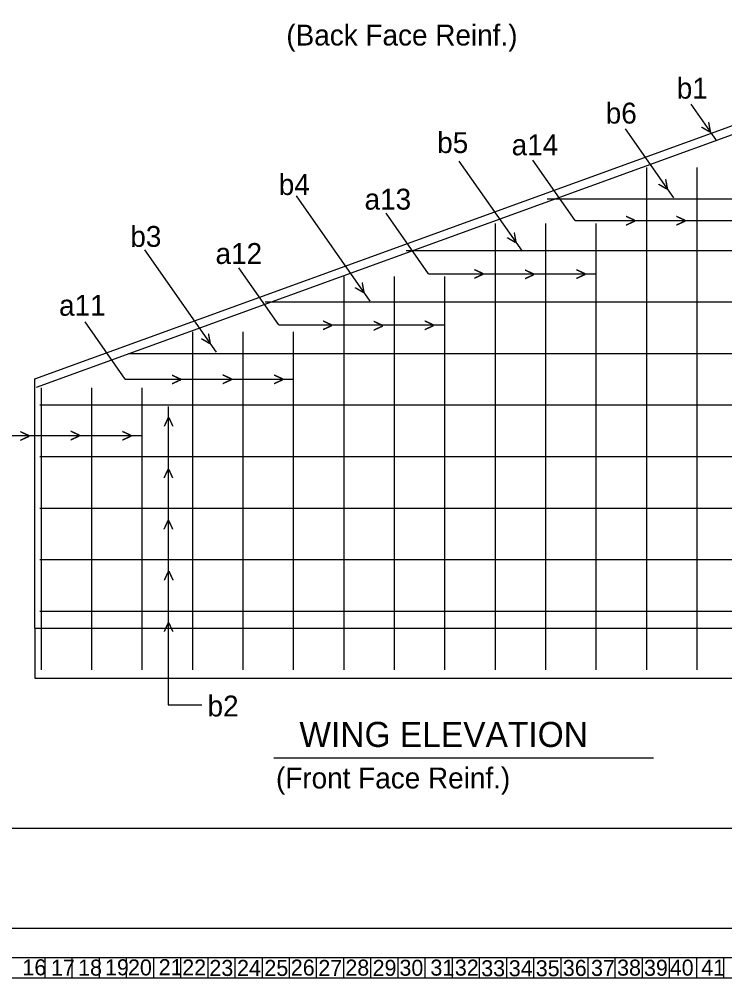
# Model space of a CAD drawing. Extents: x -0.08 to 2.83, y -0.03 to 1.92.
# Drawn here: x 0.36 to 0.8, y -0.031 to 0.567 of the extents above; entities that cross this region are included whole.
import ezdxf

# ---------------------------------------------------------------- set-up
doc = ezdxf.new("R2010")
doc.units = 0
for name, color, linetype in [('16', 7, 'Continuous'), ('17', 7, 'Continuous'), ('18', 7, 'Continuous'), ('19', 7, 'Continuous'), ('20', 7, 'Continuous'), ('21', 7, 'Continuous'), ('22', 7, 'Continuous'), ('23', 7, 'Continuous'), ('24', 7, 'Continuous'), ('25', 7, 'Continuous'), ('26', 7, 'Continuous'), ('27', 7, 'Continuous'), ('28', 7, 'Continuous'), ('29', 7, 'Continuous'), ('30', 7, 'Continuous'), ('31', 7, 'Continuous'), ('32', 7, 'Continuous'), ('33', 7, 'Continuous'), ('34', 7, 'Continuous'), ('35', 7, 'Continuous'), ('36', 7, 'Continuous'), ('37', 7, 'Continuous'), ('38', 7, 'Continuous'), ('39', 7, 'Continuous'), ('40', 7, 'Continuous'), ('41', 7, 'Continuous'), ('50', 7, 'Continuous'), ('51', 7, 'Continuous'), ('55', 7, 'Continuous'), ('57', 7, 'Continuous'), ('62', 7, 'Continuous'), ('63', 7, 'Continuous')]:
    doc.layers.add(name, color=color, linetype=linetype)

msp = doc.modelspace()

# ---------------------------------------------------------------- linework, layer by layer
at = {"layer": '50'}
for p, q in [((0.36956, 0.34269), (0.80997, 0.50242)), ((0.37071, 0.33757), (0.81174, 0.49752)), ((0.36956, 0.18732), (0.36956, 0.34269)), ((0.36956, 0.18732), (0.36956, 0.15607)), ((0.36956, 0.18732), (0.91992, 0.18732)), ((0.36956, 0.15607), (0.88809, 0.15607))]:
    msp.add_line(p, q, dxfattribs=at)
at = {"layer": '51'}
for p, q in [((0.75129, 0.16127), (0.75129, 0.47444)), ((0.78275, 0.16127), (0.78275, 0.47444)), ((0.81865, 0.45467), (0.68924, 0.45467)), ((0.65689, 0.16127), (0.65689, 0.43955)), ((0.68835, 0.16127), (0.68835, 0.43955)), ((0.71982, 0.16127), (0.71982, 0.43955)), ((0.81865, 0.42255), (0.6013, 0.42255)), ((0.56249, 0.16127), (0.56249, 0.40646)), ((0.59395, 0.16127), (0.59395, 0.40646)), ((0.62542, 0.16127), (0.62542, 0.40646)), ((0.81865, 0.39044), (0.51335, 0.39044)), ((0.46809, 0.16127), (0.46809, 0.37202)), ((0.49955, 0.16127), (0.49955, 0.37202)), ((0.53102, 0.16127), (0.53102, 0.37202)), ((0.81865, 0.35832), (0.42799, 0.35832)), ((0.37369, 0.16127), (0.37369, 0.33714)), ((0.40515, 0.16127), (0.40515, 0.33714)), ((0.43662, 0.16127), (0.43662, 0.33714)), ((0.81865, 0.3262), (0.37282, 0.3262)), ((0.81865, 0.29408), (0.37282, 0.29408)), ((0.81865, 0.26196), (0.37282, 0.26196)), ((0.81865, 0.22984), (0.37282, 0.22984)), ((0.81865, 0.19773), (0.37282, 0.19773)), ((0.37369, 0.16127), (0.37369, 0.16127)), ((0.40515, 0.16127), (0.40515, 0.16127)), ((0.43663, 0.16127), (0.43663, 0.16127)), ((0.4681, 0.16127), (0.4681, 0.16127)), ((0.46968, 0.16127), (0.46968, 0.16127)), ((0.50115, 0.16127), (0.50115, 0.16127)), ((0.56253, 0.16127), (0.56253, 0.16127)), ((0.59399, 0.16127), (0.59399, 0.16127)), ((0.62547, 0.16127), (0.62547, 0.16127)), ((0.65694, 0.16127), (0.65694, 0.16127)), ((0.68842, 0.16127), (0.68842, 0.16127)), ((0.71989, 0.16127), (0.71989, 0.16127)), ((0.75136, 0.16127), (0.75136, 0.16127)), ((0.78284, 0.16127), (0.78284, 0.16127))]:
    msp.add_line(p, q, dxfattribs=at)
at = {"layer": '55'}
for p, q in [((0.79494, 0.49115), (0.77896, 0.514)), ((0.76814, 0.45556), (0.73803, 0.49858)), ((0.67373, 0.42224), (0.63436, 0.4785)), ((0.70674, 0.44133), (0.68028, 0.47914)), ((0.57888, 0.39108), (0.53294, 0.4567)), ((0.6152, 0.40819), (0.58868, 0.44609)), ((0.70674, 0.44133), (0.81422, 0.44133)), ((0.48299, 0.35926), (0.43827, 0.42317)), ((0.5218, 0.37627), (0.49689, 0.41186)), ((0.6152, 0.40819), (0.71983, 0.40819)), ((0.42604, 0.34258), (0.40106, 0.37828)), ((0.5218, 0.37627), (0.62524, 0.37627)), ((0.42604, 0.34258), (0.53126, 0.34258)), ((0.45288, 0.32544), (0.45288, 0.13949)), ((0.34063, 0.3074), (0.43662, 0.3074))]:
    msp.add_line(p, q, dxfattribs=at)
at = {"layer": '57'}
for p, q in [((0.45288, 0.13949), (0.47372, 0.13949)), ((0.51877, 0.10649), (0.75544, 0.10649))]:
    msp.add_line(p, q, dxfattribs=at)
at = {"layer": '62'}
for p, q in [((0.10494, -0.01804), (1.17174, -0.01804)), ((0.37588, -0.01804), (0.37588, -0.03074)), ((0.39281, -0.01804), (0.39281, -0.03074)), ((0.40974, -0.01804), (0.40974, -0.03074)), ((0.42668, -0.01804), (0.42668, -0.03074)), ((0.44361, -0.01804), (0.44361, -0.03074)), ((0.46054, -0.01804), (0.46054, -0.03074)), ((0.47748, -0.01804), (0.47748, -0.03074)), ((0.49441, -0.01804), (0.49441, -0.03074)), ((0.51134, -0.01804), (0.51134, -0.03074)), ((0.52828, -0.01804), (0.52828, -0.03074)), ((0.54521, -0.01804), (0.54521, -0.03074)), ((0.56214, -0.01804), (0.56214, -0.03074)), ((0.57908, -0.01804), (0.57908, -0.03074)), ((0.59601, -0.01804), (0.59601, -0.03074)), ((0.61294, -0.01804), (0.61294, -0.03074)), ((0.62988, -0.01804), (0.62988, -0.03074)), ((0.64681, -0.01804), (0.64681, -0.03074)), ((0.66374, -0.01804), (0.66374, -0.03074)), ((0.68068, -0.01804), (0.68068, -0.03074)), ((0.69761, -0.01804), (0.69761, -0.03074)), ((0.71454, -0.01804), (0.71454, -0.03074)), ((0.73147, -0.01804), (0.73147, -0.03074)), ((0.74841, -0.01804), (0.74841, -0.03074)), ((0.76534, -0.01804), (0.76534, -0.03074)), ((0.78228, -0.01804), (0.78228, -0.03074)), ((0.79921, -0.01804), (0.79921, -0.03074)), ((0.10494, -0.03074), (1.17174, -0.03074))]:
    msp.add_line(p, q, dxfattribs=at)
at = {"layer": '63'}
msp.add_line((2.83333, 0), (0, 0), dxfattribs=at)
msp.add_lwpolyline([(0.16668, 0.06244), (0.16668, 1.77077), (2.72918, 1.77077), (2.72918, 0.10411), (2.56251, 0.10411), (2.56251, 0.14578), (2.07387, 0.14578), (2.07387, 0.06244)], close=True, dxfattribs=at)

# ---------------------------------------------------------------- texts
at = {"layer": '16'}
msp.add_text('16', height=0.01, rotation=360, dxfattribs=at).set_placement((0.3619, -0.02918))
at = {"layer": '17'}
msp.add_text('17', height=0.01, rotation=360, dxfattribs=at).set_placement((0.3797, -0.02946))
at = {"layer": '18'}
msp.add_text('18', height=0.01, rotation=360, dxfattribs=at).set_placement((0.39663, -0.02938))
at = {"layer": '19'}
msp.add_text('19', height=0.01, rotation=360, dxfattribs=at).set_placement((0.4134, -0.02918))
at = {"layer": '20'}
msp.add_text('20', height=0.01, rotation=360, dxfattribs=at).set_placement((0.42774, -0.02926))
at = {"layer": '21'}
msp.add_text('21', height=0.01, rotation=360, dxfattribs=at).set_placement((0.44688, -0.02909))
at = {"layer": '22'}
msp.add_text('22', height=0.01, rotation=360, dxfattribs=at).set_placement((0.46158, -0.02929))
at = {"layer": '23'}
msp.add_text('23', height=0.01, rotation=360, dxfattribs=at).set_placement((0.47852, -0.02958))
at = {"layer": '24'}
msp.add_text('24', height=0.01, rotation=360, dxfattribs=at).set_placement((0.49576, -0.02958))
at = {"layer": '25'}
msp.add_text('25', height=0.01, rotation=360, dxfattribs=at).set_placement((0.51281, -0.02958))
at = {"layer": '26'}
msp.add_text('26', height=0.01, rotation=360, dxfattribs=at).set_placement((0.52931, -0.02936))
at = {"layer": '27'}
msp.add_text('27', height=0.01, rotation=360, dxfattribs=at).set_placement((0.54648, -0.02958))
at = {"layer": '28'}
msp.add_text('28', height=0.01, rotation=360, dxfattribs=at).set_placement((0.56333, -0.02938))
at = {"layer": '29'}
msp.add_text('29', height=0.01, rotation=360, dxfattribs=at).set_placement((0.58032, -0.02956))
at = {"layer": '30'}
msp.add_text('30', height=0.01, rotation=360, dxfattribs=at).set_placement((0.59706, -0.02946))
at = {"layer": '31'}
msp.add_text('31', height=0.01, rotation=360, dxfattribs=at).set_placement((0.61636, -0.02938))
at = {"layer": '32'}
msp.add_text('32', height=0.01, rotation=360, dxfattribs=at).set_placement((0.63163, -0.02938))
at = {"layer": '33'}
msp.add_text('33', height=0.01, rotation=360, dxfattribs=at).set_placement((0.64808, -0.02978))
at = {"layer": '34'}
msp.add_text('34', height=0.01, rotation=360, dxfattribs=at).set_placement((0.66527, -0.02978))
at = {"layer": '35'}
msp.add_text('35', height=0.01, rotation=360, dxfattribs=at).set_placement((0.68209, -0.02978))
at = {"layer": '36'}
msp.add_text('36', height=0.01, rotation=360, dxfattribs=at).set_placement((0.69895, -0.02958))
at = {"layer": '37'}
msp.add_text('37', height=0.01, rotation=360, dxfattribs=at).set_placement((0.71654, -0.02958))
at = {"layer": '38'}
msp.add_text('38', height=0.01, rotation=360, dxfattribs=at).set_placement((0.73281, -0.02938))
at = {"layer": '39'}
msp.add_text('39', height=0.01, rotation=360, dxfattribs=at).set_placement((0.74958, -0.0295))
at = {"layer": '40'}
msp.add_text('40', height=0.01, rotation=360, dxfattribs=at).set_placement((0.76566, -0.02938))
at = {"layer": '41'}
msp.add_text('41', height=0.01, rotation=360, dxfattribs=at).set_placement((0.78528, -0.02938))
at = {"layer": '55'}
for height, rotation, p in [(0.00867, 304.99202, (0.78393, 0.49934)), (0.00867, 304.99202, (0.78393, 0.49934)), (0.00868, 305.01306, (0.75713, 0.46374)), (0.00868, 305.01306, (0.75713, 0.46374)), (0.00867, 304.99202, (0.66271, 0.43043)), (0.00867, 304.99202, (0.66271, 0.43043)), (0.00868, 305.01306, (0.56786, 0.39925)), (0.00868, 305.01306, (0.56786, 0.39925)), (0.00867, 304.99202, (0.47198, 0.36744)), (0.00867, 304.99202, (0.47198, 0.36744)), (0.00868, 90, (0.45722, 0.31242)), (0.00868, 90, (0.45722, 0.31242)), (0.00868, 90, (0.45708, 0.28024)), (0.00868, 90, (0.45708, 0.28024)), (0.00868, 90, (0.45708, 0.24833)), (0.00868, 90, (0.45708, 0.24833)), (0.00868, 90, (0.45728, 0.21659)), (0.00868, 90, (0.45728, 0.21659)), (0.00868, 90, (0.45719, 0.18445)), (0.00868, 90, (0.45719, 0.18445))]:
    msp.add_text('>', height=height, rotation=rotation, dxfattribs=at).set_placement(p)
for p in [(0.73786, 0.43714), (0.73786, 0.43714), (0.7692, 0.43714), (0.7692, 0.43714), (0.64314, 0.40397), (0.64314, 0.40397), (0.67475, 0.40369), (0.67475, 0.40369), (0.70681, 0.40386), (0.70681, 0.40386), (0.54873, 0.37194), (0.54873, 0.37194), (0.58048, 0.37166), (0.58048, 0.37166), (0.61223, 0.37194), (0.61223, 0.37194), (0.45452, 0.33814), (0.45452, 0.33814), (0.48627, 0.33829), (0.48627, 0.33829), (0.51824, 0.33824), (0.51824, 0.33824), (0.35996, 0.30293), (0.35996, 0.30293), (0.39144, 0.3032), (0.39144, 0.3032), (0.4236, 0.30307), (0.4236, 0.30307)]:
    msp.add_text('>', height=0.00868, dxfattribs=at).set_placement(p)
at = {"layer": '57'}
for s, height, p in [('(Back Face Reinf.)', 0.0130208, (0.5265, 0.55051)), ('b1', 0.013017, (0.77003, 0.51739)), ('b6', 0.013017, (0.72573, 0.50186)), ('b5', 0.013017, (0.62061, 0.48346)), ('a14', 0.013017, (0.66703, 0.48209)), ('b4', 0.013017, (0.5218, 0.45733)), ('a13', 0.013017, (0.57529, 0.44821)), ('b3', 0.013017, (0.4292, 0.42499)), ('a12', 0.013017, (0.48234, 0.41434)), ('a11', 0.013017, (0.38474, 0.38205)), ('b2', 0.013017, (0.47737, 0.1322)), ('WING ELEVATION', 0.015625, (0.53466, 0.1132)), ('(Front Face Reinf.)', 0.0130208, (0.52004, 0.08733))]:
    msp.add_text(s, height=height, dxfattribs=at).set_placement(p)

doc.saveas('drawing.dxf')
